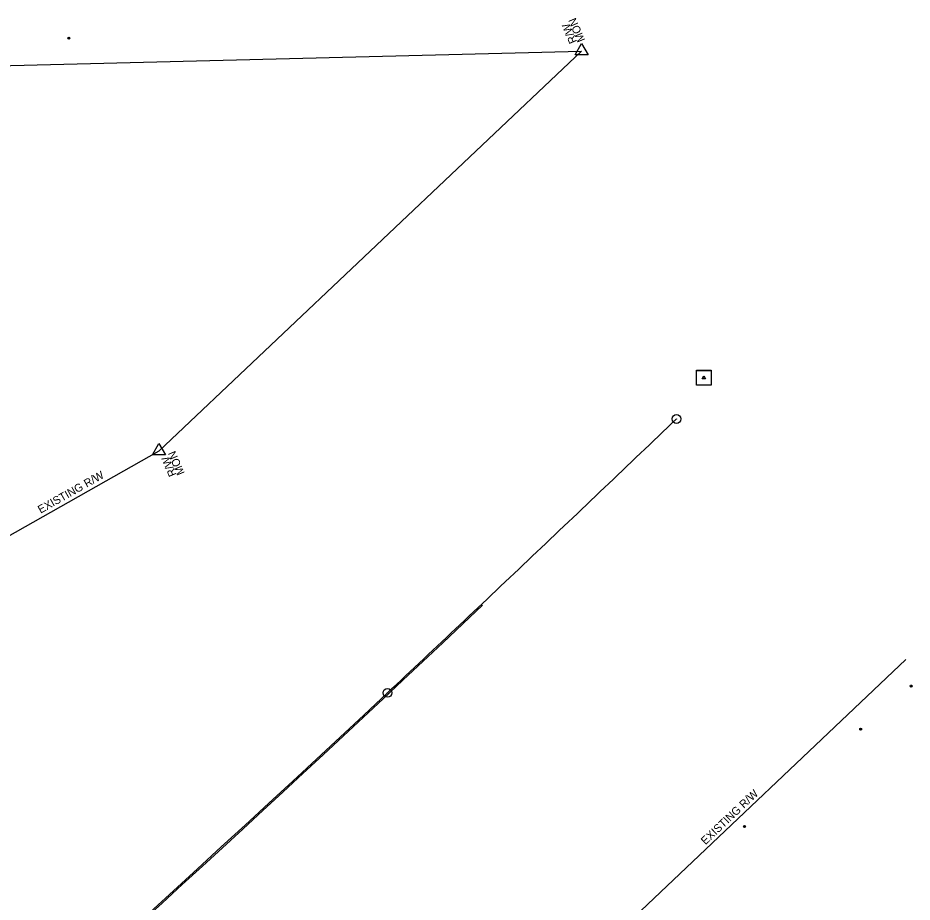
# Model space of a CAD drawing. Extents: x 1550153 to 1552579, y 809637 to 812160.
# Drawn here: x 1551894.8 to 1552343.9, y 810857.2 to 811301.3 of the extents above; entities that cross this region are included whole.
import ezdxf

# ---------------------------------------------------------------- set-up
doc = ezdxf.new("R2010")
doc.units = 0
for name, color, linetype in [('CTL Secondary Horizontal and Vertical CELL', 7, 'Continuous'), ('Default', 7, 'Continuous'), ('E_NCDOT_Horizontal_Alignment', 7, 'Continuous'), ('E_NCDOT_Horizontal_Alignment_Curve', 7, 'Continuous'), ('E_NCDOT_Horizontal_Alignment_Spiral', 7, 'Continuous'), ('E_NCDOT_Horizontal_Alignment_Tick_Label', 7, 'Continuous'), ('Exist Property Line', 7, 'Continuous'), ('Exist Right of Way Line', 7, 'Continuous'), ('Exist Right of Way Line Text', 7, 'Continuous'), ('Exist Right of Way Monument CELL', 7, 'Continuous'), ('Exist Right of Way Monument Text', 7, 'Continuous')]:
    doc.layers.add(name, color=color, linetype=linetype)

# ---------------------------------------------------------------- blocks, each defined once
blk = doc.blocks.new('SurveyPointCell')
at = {"layer": 'Default'}
for p, q in [((-0.5, 0), (0.5, 0)), ((0, -0.5), (0, 0.5))]:
    blk.add_line(p, q, dxfattribs=at)
blk.add_circle((0, 0), 0.5, dxfattribs=at)
blk = doc.blocks.new('SurveyControlPointCell')
at = {"layer": 'Default'}
for p, q in [((-0.87, -0.5), (0, 1)), ((0, 1), (0.87, -0.5)), ((0.87, -0.5), (-0.87, -0.5))]:
    blk.add_line(p, q, dxfattribs=at)
blk.add_circle((0, 0), 0.5, dxfattribs=at)

msp = doc.modelspace()

# ---------------------------------------------------------------- linework, layer by layer
at = {"layer": 'CTL Secondary Horizontal and Vertical CELL'}
for p, q in [((1552239.25, 811120.54), (1552239.25, 811120.54)), ((1552239.26, 811120.53), (1552239.26, 811120.53))]:
    msp.add_line(p, q, dxfattribs=at)
for points in [[(1552235.58, 811124.24), (1552242.99, 811124.24), (1552242.99, 811116.81), (1552235.58, 811116.81)], [(1552235.58, 811124.23), (1552243, 811124.23), (1552243, 811116.81), (1552235.58, 811116.81)]]:
    msp.add_lwpolyline(points, close=True, dxfattribs=at)
at = {"layer": 'Default'}
msp.add_line((1552239.25, 811120.54), (1552239.25, 811120.54), dxfattribs=at)
msp.add_arc((1544558.52, 818987.58), 11000, 308.905285, 313.48368, dxfattribs=at)
msp.add_arc((1544558.52, 818987.58), 11000, 308.905285, 313.48368, dxfattribs=at)
at = {"layer": 'E_NCDOT_Horizontal_Alignment'}
for centre, radius in [((1552225.53, 811099.81), 2.2), ((1552225.53, 811099.81), 0.0707), ((1552080.38, 810962.22), 2.2), ((1552080.38, 810962.22), 0.0707)]:
    msp.add_circle(centre, radius, dxfattribs=at)
at = {"layer": 'E_NCDOT_Horizontal_Alignment_Curve'}
msp.add_arc((1544245.73, 819324.67), 11459.16, 307.933611, 313.133611, dxfattribs=at)
msp.add_arc((1544245.73, 819324.67), 11459.16, 307.933611, 313.133611, dxfattribs=at)
at = {"layer": 'E_NCDOT_Horizontal_Alignment_Spiral'}
msp.add_open_spline([(1552080.38, 810962.22), (1552092.54, 810973.62), (1552116.82, 810996.46), (1552153.12, 811030.85), (1552189.35, 811065.3), (1552213.47, 811088.31), (1552225.53, 811099.81)], degree=3, dxfattribs=at)
msp.add_open_spline([(1552080.38, 810962.22), (1552092.54, 810973.62), (1552116.82, 810996.46), (1552153.12, 811030.85), (1552189.35, 811065.3), (1552213.47, 811088.31), (1552225.53, 811099.81)], degree=3, dxfattribs=at)
at = {"layer": 'E_NCDOT_Horizontal_Alignment_Tick_Label'}
msp.add_arc((1544558.52, 818987.58), 11000, 308.905285, 313.48368, dxfattribs=at)
at = {"layer": 'Exist Property Line'}
msp.add_line((1551711.09, 811272.74), (1552177.91, 811284.58), dxfattribs=at)
at = {"layer": 'Exist Right of Way Line'}
for p, q in [((1552177.91, 811284.58), (1551965.65, 811083.67)), ((1551965.65, 811083.67), (1551789.31, 810984.03)), ((1552193.24, 810839.16), (1552340.77, 810978.94))]:
    msp.add_line(p, q, dxfattribs=at)
at = {"layer": 'Exist Right of Way Monument CELL'}
for p, q in [((1552177.91, 811284.58), (1552177.91, 811284.58)), ((1552177.91, 811284.58), (1552177.91, 811284.58)), ((1552177.91, 811284.58), (1552177.91, 811284.58)), ((1551965.65, 811083.67), (1551965.65, 811083.67)), ((1551965.65, 811083.67), (1551965.65, 811083.67))]:
    msp.add_line(p, q, dxfattribs=at)
for points in [[(1552174.66, 811282.69), (1552177.91, 811288.33), (1552181.16, 811282.69)], [(1552174.66, 811282.69), (1552177.91, 811288.33), (1552181.16, 811282.69)], [(1552174.66, 811282.69), (1552177.91, 811288.33), (1552181.16, 811282.69)], [(1551962.4, 811081.78), (1551965.65, 811087.42), (1551968.9, 811081.78)], [(1551962.4, 811081.78), (1551965.65, 811087.42), (1551968.9, 811081.78)]]:
    msp.add_lwpolyline(points, close=True, dxfattribs=at)

# ---------------------------------------------------------------- block references
at = {"layer": 'Default'}
for name, p in [('SurveyPointCell', (1551920.36, 811291.06)), ('SurveyPointCell', (1551920.36, 811291.06)), ('SurveyControlPointCell', (1552239.26, 811120.53)), ('SurveyPointCell', (1552343.35, 810965.68)), ('SurveyPointCell', (1552343.36, 810965.68)), ('SurveyPointCell', (1552318.02, 810943.98)), ('SurveyPointCell', (1552318.02, 810943.98)), ('SurveyPointCell', (1552259.71, 810895.1)), ('SurveyPointCell', (1552259.72, 810895.11))]:
    msp.add_blockref(name, p, dxfattribs=at)

# ---------------------------------------------------------------- texts
at = {"layer": 'Exist Right of Way Line Text'}
for rotation, p in [(29.4675, (1551906.22, 811052.21)), (43.4835, (1552240.08, 810885.69))]:
    msp.add_text('EXISTING R/W', height=4.02, rotation=rotation, dxfattribs=at).set_placement(p)
at = {"layer": 'Exist Right of Way Monument Text'}
for s, p in [('MON', (1552179.74, 811290.13)), ('R/W', (1552175.66, 811289.36)), ('MON', (1551978.66, 811072.64)), ('R/W', (1551974.59, 811071.88))]:
    msp.add_text(s, height=4.02, rotation=113.1736, dxfattribs=at).set_placement(p)

doc.saveas('drawing.dxf')
